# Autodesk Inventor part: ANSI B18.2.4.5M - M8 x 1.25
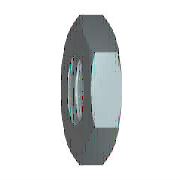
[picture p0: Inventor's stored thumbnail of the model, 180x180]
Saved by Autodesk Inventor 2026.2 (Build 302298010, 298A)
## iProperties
Created: 2025-01
Part Number: ANSI B18.2.4.5M - M8 x 1.25
Material: 강철, 연강
Description: 6각 잼 너트
Document SubType Name: Modeling
Standard: ANSI B18.2.4.5M
Designer: work
Standard Revision: 2008
Standards Organization: ANSI
Language: ko-KR
Size Designation: M8 x 1.25
Categories: <MemberInstance><Categories><Category DisplayName="조임쇠" InternalName="e4da775c-781d-43d5-af7c-5136215cf5a6" Mnemonic="FSTN"><Category DisplayName="너트" InternalN
Density: 7.85 g/cm^3
Appearance: 반연마
IsCustomPart: 1
Author: work
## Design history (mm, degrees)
body "Solid1"
workaxis "Work Axis1"
workplane "Work Plane1"
sketch "스케치1"
  geometry: L1 (-7.506, 0)-(-3.753, 6.5); L2 (-3.753, 6.5)-(3.753, 6.5); L3 (3.753, 6.5)-(7.506, 0); L4 (7.506, 0)-(3.753, -6.5); L5 (3.753, -6.5)-(-3.753, -6.5); L6 (-3.753, -6.5)-(-7.506, 0); 2 further points
  constraints: 12 end point, 1 coincident, 1 horizontal, 11 other
  dimensions: "d0" = 15.01111 distance of L3.end L1.start (= 1.1547 x SW)
extrude "본체" new body sketch "스케치1" distance "d1" = 4 (= KOH); taper "d2" = 0 deg
revolve "모따기1" stored, may be unused: angle "d7" = 90 deg
sketch "스케치3"
  geometry: A1 r 6.5 centre (0, 0) between (-3.25, -5.629) and (3.25, -5.629) reference; 1 further point
  constraints: 1 coincident
hole "스레드" sketch "스케치3" diameter "d25" = 6.647; stored, may be unused: countersink angle "d29" = 82 deg, drill point angle "d31" = 118 deg; dims "d26" = 6, "d27" = 4, "d28" = 2, "d30" = 8
chamfer "모따기2" distance "d8" = 0.67658 (= -0.5 x GD1 + 0.5 x NND); stored, may be unused: angle "d9" = 30 deg, second distance "d40" = 0.67658 (= -0.5 x GD1 + 0.5 x NND)
chamfer "모따기3" distance "d10" = 0.67658 (= -0.5 x GD1 + 0.5 x NND); stored, may be unused: angle "d11" = 30 deg, second distance "d41" = 0.67658 (= -0.5 x GD1 + 0.5 x NND)
sketch "스케치2"
  geometry: L1 (0, 3.753)-(0, 7.506) reference; L2 (0, 7.506)-(4, 7.506) reference; L3 (4, 3.753)-(4, 7.506) reference; L4 (-0.8, 0)-(4.8, 0) reference; L5 (0.581, 7.506)-(0, 6.5); L6 (3.419, 7.506)-(4, 6.5)
  constraints: 4 end point, 4 point on line
  dimensions: "d3" = 30 deg angle of L1 L5 (= ANG1); "d4" = 30 deg angle of L3 L6 (= ANG2); "d5" = 13 diameter of L5.end L4 (= SW0); "d6" = 13 diameter of L6.end L4 (= SW01)
other parameters: "ANG1" = 30 deg [user parameter; used in 1 equation term], "ANG2" = 30 deg [user parameter; used in 1 equation term], "NND" = 8 [user parameter; used in 4 equation terms], "KOH" = 4 [user parameter; used in 1 equation term], "SW" = 13 [user parameter; used in 4 equation terms], "SW0" = 13 (= SW) [user parameter; used in 1 equation term], "SW01" = 13 (= SW) [user parameter; used in 1 equation term], "GD1" = 6.64684 (computed from THREADDIA, PTC, TOA) [user parameter; used in 4 equation terms], "d13" = 0, "d14" = 0, "d39" = 0, "d42" = 0, "GUL" = 0.67658 (= 0.541266 x PTC) [user parameter], "TPU" = 8 (computed from PTC) [user parameter], "THREADDIA" = 8 [user parameter; used in 1 equation term], "TOA" = 30 deg [user parameter; used in 1 equation term], "PTC" = 1.25 [user parameter; used in 4 equation terms], "E0" = 15.015 (= 1.155 x SW) [user parameter], "GAL" = 0.67658 (= 0.541266 x PTC) [user parameter]
